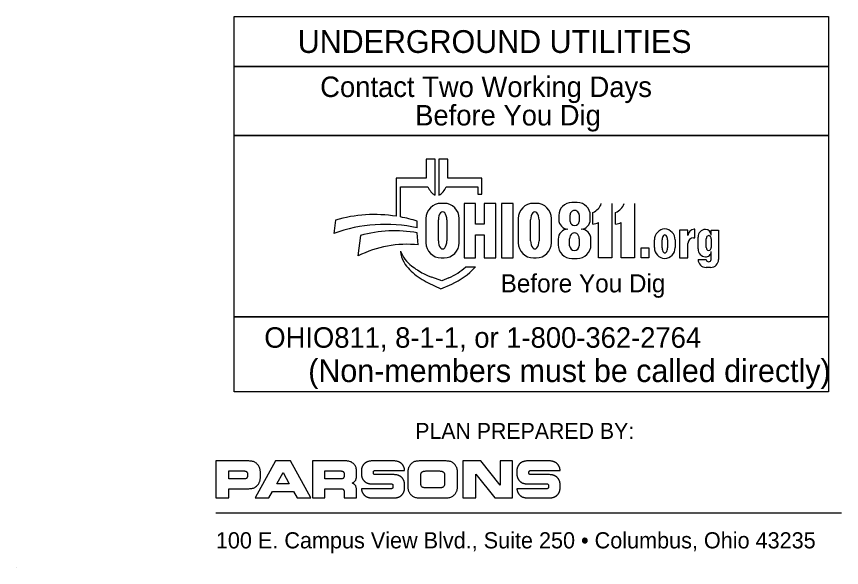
# Model space of a CAD drawing. Extents: x 2080852 to 2433556, y 1080825 to 1306626.
# Drawn here: x 2080852 to 2157439, y 1087161 to 1138301 of the extents above; entities that cross this region are included whole.
import ezdxf

# ---------------------------------------------------------------- set-up
doc = ezdxf.new("R2010")
doc.units = 0
for name, color, linetype in [('PM_P_Chevron_Line', 7, 'Continuous'), ('PM_P_Lane_Line', 7, 'Continuous'), ('SC_Scratch1', 7, 'Continuous')]:
    doc.layers.add(name, color=color, linetype=linetype)

msp = doc.modelspace()

# ---------------------------------------------------------------- linework, layer by layer
at = {"layer": 'PM_P_Chevron_Line'}
for p, q in [((2102311, 1097050), (2099359, 1097050)), ((2104904, 1097050), (2103010, 1093621)), ((2106284, 1097050), (2104904, 1097050)), ((2108178, 1093621), (2106284, 1097050)), ((2111445, 1097050), (2108340, 1097050)), ((2108340, 1097050), (2108340, 1093621)), ((2115910, 1097050), (2113838, 1097050)), ((2120622, 1097050), (2118351, 1097050)), ((2123968, 1097050), (2122290, 1097050)), ((2122290, 1097050), (2122290, 1093621)), ((2125761, 1094812), (2123968, 1097050)), ((2125761, 1097050), (2125761, 1094812)), ((2126893, 1097050), (2125761, 1097050)), ((2126893, 1093621), (2126893, 1097050)), ((2130345, 1097050), (2128273, 1097050)), ((2100576, 1095380), (2100576, 1096117)), ((2100576, 1096117), (2102002, 1096117)), ((2103496, 1095549), (2103496, 1095976)), ((2105012, 1094936), (2105594, 1095990)), ((2105594, 1095990), (2106176, 1094936)), ((2109475, 1095380), (2109475, 1096117)), ((2109475, 1096117), (2110974, 1096117)), ((2112414, 1095633), (2112414, 1096082)), ((2112874, 1096117), (2112874, 1095853)), ((2113987, 1095944), (2113987, 1095994)), ((2114158, 1096159), (2116875, 1096159)), ((2117166, 1095976), (2117166, 1094695)), ((2118857, 1096117), (2120120, 1096117)), ((2121806, 1094695), (2121806, 1095976)), ((2127309, 1096117), (2127309, 1095853)), ((2128422, 1095944), (2128422, 1095994)), ((2128593, 1096159), (2131309, 1096159)), ((2102002, 1095380), (2100576, 1095380)), ((2102287, 1095896), (2102287, 1095602)), ((2110974, 1095380), (2109475, 1095380)), ((2111259, 1095896), (2111259, 1095602)), ((2115910, 1095779), (2114158, 1095779)), ((2118391, 1094928), (2118391, 1095735)), ((2120586, 1095735), (2120586, 1094928)), ((2123484, 1093621), (2123484, 1095817)), ((2123484, 1095817), (2125243, 1093621)), ((2130345, 1095779), (2128593, 1095779)), ((2100576, 1093621), (2100576, 1094475)), ((2100576, 1094475), (2102311, 1094475)), ((2106176, 1094936), (2105012, 1094936)), ((2109475, 1093621), (2109475, 1094475)), ((2109475, 1094475), (2110974, 1094475)), ((2115632, 1094475), (2112874, 1094475)), ((2113838, 1094920), (2115632, 1094920)), ((2115803, 1094755), (2115803, 1094640)), ((2116875, 1094512), (2116875, 1094888)), ((2120120, 1094546), (2118857, 1094546)), ((2130067, 1094475), (2127309, 1094475)), ((2128273, 1094920), (2130067, 1094920)), ((2130238, 1094755), (2130238, 1094640)), ((2131309, 1094512), (2131309, 1094888)), ((2104285, 1093621), (2104606, 1094202)), ((2104606, 1094202), (2106582, 1094202)), ((2106582, 1094202), (2106903, 1093621)), ((2111259, 1094254), (2111259, 1093621)), ((2112414, 1093621), (2112414, 1094361)), ((2103010, 1093621), (2104285, 1093621)), ((2106903, 1093621), (2108178, 1093621)), ((2108340, 1093621), (2109475, 1093621)), ((2111259, 1093621), (2112414, 1093621)), ((2113838, 1093621), (2115910, 1093621)), ((2118351, 1093621), (2120622, 1093621)), ((2122290, 1093621), (2123484, 1093621)), ((2125243, 1093621), (2126893, 1093621)), ((2128273, 1093621), (2130345, 1093621)), ((2099359, 1092220), (2157439, 1092220))]:
    msp.add_line(p, q, dxfattribs=at)
msp.add_lwpolyline([(2099359, 1097050), (2099359, 1093621), (2100576, 1093621)], dxfattribs=at)
for points in [[(2103496, 1095976), (2103492, 1096063), (2103479, 1096175), (2103444, 1096329), (2103408, 1096429), (2103370, 1096510), (2103303, 1096629), (2103226, 1096727), (2103118, 1096829), (2102979, 1096929), (2102853, 1096988), (2102694, 1097023), (2102525, 1097042), (2102311, 1097050)], [(2112414, 1096082), (2112409, 1096239), (2112398, 1096327), (2112370, 1096432), (2112320, 1096560), (2112249, 1096671), (2112165, 1096770), (2112076, 1096852), (2111973, 1096921), (2111845, 1096980), (2111707, 1097019), (2111579, 1097041), (2111445, 1097050)], [(2113145, 1096797), (2113119, 1096770), (2113075, 1096722), (2113035, 1096671), (2113015, 1096644), (2112997, 1096617), (2112980, 1096589), (2112964, 1096560), (2112956, 1096545), (2112949, 1096529), (2112936, 1096497), (2112925, 1096465), (2112914, 1096432), (2112898, 1096380), (2112892, 1096353), (2112886, 1096327), (2112882, 1096305), (2112878, 1096283), (2112875, 1096239), (2112874, 1096117)], [(2113838, 1097050), (2113705, 1097041), (2113641, 1097032), (2113609, 1097026), (2113577, 1097019), (2113507, 1097002), (2113438, 1096980), (2113405, 1096968), (2113373, 1096954), (2113311, 1096921), (2113284, 1096906), (2113258, 1096889), (2113232, 1096871), (2113207, 1096852), (2113184, 1096833), (2113162, 1096813), (2113145, 1096797)], [(2116589, 1096811), (2116587, 1096813), (2116565, 1096833), (2116541, 1096852), (2116517, 1096871), (2116491, 1096889), (2116465, 1096906), (2116438, 1096921), (2116375, 1096954), (2116343, 1096968), (2116310, 1096980), (2116242, 1097002), (2116172, 1097019), (2116140, 1097026), (2116108, 1097032), (2116044, 1097041), (2115910, 1097050)], [(2116875, 1096159), (2116874, 1096239), (2116871, 1096283), (2116867, 1096305), (2116863, 1096327), (2116857, 1096353), (2116850, 1096380), (2116835, 1096432), (2116824, 1096465), (2116812, 1096497), (2116799, 1096529), (2116792, 1096545), (2116785, 1096560), (2116769, 1096589), (2116752, 1096617), (2116733, 1096644), (2116714, 1096671), (2116673, 1096722), (2116630, 1096770), (2116589, 1096811)], [(2118351, 1097050), (2118138, 1097042), (2117968, 1097023), (2117810, 1096988), (2117684, 1096929), (2117545, 1096829), (2117437, 1096727), (2117360, 1096629), (2117293, 1096510), (2117255, 1096429), (2117218, 1096329), (2117183, 1096175), (2117170, 1096063), (2117166, 1095976)], [(2121806, 1095976), (2121803, 1096063), (2121790, 1096175), (2121755, 1096329), (2121718, 1096429), (2121680, 1096510), (2121613, 1096629), (2121536, 1096727), (2121428, 1096829), (2121289, 1096929), (2121163, 1096988), (2121005, 1097023), (2120835, 1097042), (2120622, 1097050)], [(2127580, 1096797), (2127553, 1096770), (2127510, 1096722), (2127470, 1096671), (2127450, 1096644), (2127432, 1096617), (2127415, 1096589), (2127399, 1096560), (2127391, 1096545), (2127384, 1096529), (2127371, 1096497), (2127360, 1096465), (2127349, 1096432), (2127333, 1096380), (2127327, 1096353), (2127321, 1096327), (2127316, 1096305), (2127313, 1096283), (2127310, 1096239), (2127309, 1096117)], [(2128273, 1097050), (2128140, 1097041), (2128076, 1097032), (2128044, 1097026), (2128012, 1097019), (2127942, 1097002), (2127873, 1096980), (2127840, 1096968), (2127808, 1096954), (2127745, 1096921), (2127718, 1096906), (2127692, 1096889), (2127667, 1096871), (2127642, 1096852), (2127619, 1096833), (2127596, 1096813), (2127580, 1096797)], [(2131023, 1096811), (2131022, 1096813), (2131000, 1096833), (2130976, 1096852), (2130951, 1096871), (2130926, 1096889), (2130900, 1096906), (2130873, 1096921), (2130810, 1096954), (2130778, 1096968), (2130745, 1096980), (2130676, 1097002), (2130607, 1097019), (2130575, 1097026), (2130543, 1097032), (2130479, 1097041), (2130345, 1097050)], [(2131309, 1096159), (2131309, 1096239), (2131306, 1096283), (2131302, 1096305), (2131298, 1096327), (2131292, 1096353), (2131285, 1096380), (2131269, 1096432), (2131259, 1096465), (2131247, 1096497), (2131234, 1096529), (2131227, 1096545), (2131220, 1096560), (2131204, 1096589), (2131187, 1096617), (2131168, 1096644), (2131149, 1096671), (2131108, 1096722), (2131065, 1096770), (2131023, 1096811)], [(2102002, 1096117), (2102048, 1096116), (2102159, 1096086), (2102201, 1096061), (2102246, 1096018), (2102280, 1095952), (2102287, 1095913), (2102287, 1095896)], [(2110974, 1096117), (2111020, 1096116), (2111131, 1096086), (2111173, 1096061), (2111218, 1096018), (2111252, 1095952), (2111259, 1095913), (2111259, 1095896)], [(2113987, 1095994), (2113987, 1096027), (2113989, 1096052), (2114005, 1096093), (2114033, 1096127), (2114056, 1096143), (2114105, 1096157), (2114158, 1096159)], [(2118391, 1095735), (2118394, 1095786), (2118400, 1095844), (2118417, 1095901), (2118454, 1095971), (2118515, 1096032), (2118585, 1096070), (2118639, 1096092), (2118730, 1096108), (2118857, 1096117)], [(2120120, 1096117), (2120247, 1096108), (2120339, 1096092), (2120393, 1096070), (2120463, 1096032), (2120524, 1095971), (2120560, 1095901), (2120577, 1095844), (2120584, 1095786), (2120586, 1095735)], [(2128422, 1095994), (2128422, 1096027), (2128424, 1096052), (2128440, 1096093), (2128468, 1096127), (2128491, 1096143), (2128540, 1096157), (2128593, 1096159)], [(2102287, 1095602), (2102287, 1095584), (2102280, 1095545), (2102246, 1095479), (2102201, 1095436), (2102159, 1095411), (2102048, 1095381), (2102002, 1095380)], [(2102311, 1094475), (2102525, 1094482), (2102694, 1094501), (2102853, 1094537), (2102979, 1094596), (2103118, 1094696), (2103226, 1094798), (2103303, 1094896), (2103370, 1095015), (2103408, 1095096), (2103444, 1095195), (2103479, 1095349), (2103492, 1095461), (2103496, 1095549)], [(2111259, 1095602), (2111259, 1095584), (2111252, 1095545), (2111218, 1095479), (2111173, 1095436), (2111131, 1095411), (2111020, 1095381), (2110974, 1095380)], [(2112012, 1094997), (2112107, 1095041), (2112176, 1095082), (2112242, 1095133), (2112304, 1095208), (2112340, 1095267), (2112366, 1095329), (2112398, 1095444), (2112409, 1095552), (2112414, 1095633)], [(2112874, 1095853), (2112875, 1095730), (2112878, 1095687), (2112882, 1095665), (2112886, 1095643), (2112892, 1095616), (2112898, 1095590), (2112914, 1095537), (2112925, 1095505), (2112936, 1095472), (2112949, 1095441), (2112956, 1095425), (2112964, 1095409), (2112980, 1095380), (2112997, 1095353), (2113015, 1095326), (2113035, 1095299), (2113075, 1095248), (2113119, 1095199), (2113145, 1095173)], [(2114158, 1095779), (2114105, 1095781), (2114056, 1095795), (2114033, 1095811), (2114005, 1095845), (2113989, 1095886), (2113987, 1095911), (2113987, 1095944)], [(2116589, 1095541), (2116587, 1095542), (2116565, 1095562), (2116541, 1095581), (2116517, 1095600), (2116491, 1095618), (2116465, 1095635), (2116438, 1095651), (2116375, 1095683), (2116343, 1095697), (2116310, 1095709), (2116242, 1095731), (2116172, 1095748), (2116140, 1095755), (2116108, 1095761), (2116044, 1095770), (2115910, 1095779)], [(2116875, 1094888), (2116874, 1094969), (2116871, 1095012), (2116867, 1095034), (2116863, 1095056), (2116857, 1095082), (2116850, 1095109), (2116835, 1095162), (2116824, 1095194), (2116812, 1095226), (2116799, 1095258), (2116792, 1095274), (2116785, 1095290), (2116769, 1095318), (2116752, 1095346), (2116733, 1095373), (2116714, 1095400), (2116673, 1095451), (2116630, 1095499), (2116589, 1095541)], [(2127309, 1095853), (2127310, 1095730), (2127313, 1095687), (2127316, 1095665), (2127321, 1095643), (2127327, 1095616), (2127333, 1095590), (2127349, 1095537), (2127360, 1095505), (2127371, 1095472), (2127384, 1095441), (2127391, 1095425), (2127399, 1095409), (2127415, 1095380), (2127432, 1095353), (2127450, 1095326), (2127470, 1095299), (2127510, 1095248), (2127553, 1095199), (2127580, 1095173)], [(2128593, 1095779), (2128540, 1095781), (2128491, 1095795), (2128468, 1095811), (2128440, 1095845), (2128424, 1095886), (2128422, 1095911), (2128422, 1095944)], [(2131023, 1095541), (2131022, 1095542), (2131000, 1095562), (2130976, 1095581), (2130951, 1095600), (2130926, 1095618), (2130900, 1095635), (2130873, 1095651), (2130810, 1095683), (2130778, 1095697), (2130745, 1095709), (2130676, 1095731), (2130607, 1095748), (2130575, 1095755), (2130543, 1095761), (2130479, 1095770), (2130345, 1095779)], [(2131309, 1094888), (2131309, 1094969), (2131306, 1095012), (2131302, 1095034), (2131298, 1095056), (2131292, 1095082), (2131285, 1095109), (2131269, 1095162), (2131259, 1095194), (2131247, 1095226), (2131234, 1095258), (2131227, 1095274), (2131220, 1095290), (2131204, 1095318), (2131187, 1095346), (2131168, 1095373), (2131149, 1095400), (2131108, 1095451), (2131065, 1095499), (2131023, 1095541)], [(2110974, 1094475), (2111020, 1094474), (2111131, 1094444), (2111173, 1094419), (2111218, 1094376), (2111252, 1094310), (2111259, 1094271), (2111259, 1094254)], [(2112414, 1094361), (2112409, 1094442), (2112398, 1094550), (2112366, 1094665), (2112340, 1094727), (2112304, 1094786), (2112242, 1094861), (2112176, 1094912), (2112107, 1094953), (2112012, 1094997)], [(2112874, 1094475), (2112875, 1094431), (2112878, 1094388), (2112882, 1094366), (2112886, 1094344), (2112892, 1094318), (2112898, 1094291), (2112914, 1094238), (2112925, 1094206), (2112936, 1094174), (2112949, 1094142), (2112956, 1094126), (2112964, 1094110), (2112980, 1094081), (2112997, 1094054), (2113015, 1094027), (2113035, 1094000), (2113075, 1093949), (2113119, 1093901), (2113162, 1093858), (2113174, 1093847)], [(2113145, 1095173), (2113162, 1095157), (2113184, 1095137), (2113207, 1095118), (2113232, 1095099), (2113258, 1095081), (2113284, 1095064), (2113311, 1095048), (2113373, 1095016), (2113405, 1095002), (2113438, 1094990), (2113507, 1094968), (2113577, 1094951), (2113609, 1094944), (2113641, 1094938), (2113705, 1094929), (2113838, 1094920)], [(2115632, 1094920), (2115685, 1094918), (2115734, 1094904), (2115757, 1094888), (2115785, 1094853), (2115801, 1094813), (2115803, 1094787), (2115803, 1094755)], [(2115803, 1094640), (2115803, 1094607), (2115801, 1094582), (2115785, 1094541), (2115757, 1094507), (2115734, 1094491), (2115685, 1094477), (2115632, 1094475)], [(2116589, 1093859), (2116630, 1093901), (2116673, 1093949), (2116714, 1094000), (2116733, 1094027), (2116752, 1094054), (2116769, 1094081), (2116785, 1094110), (2116792, 1094126), (2116799, 1094142), (2116812, 1094174), (2116824, 1094206), (2116835, 1094238), (2116850, 1094291), (2116857, 1094318), (2116863, 1094344), (2116867, 1094366), (2116871, 1094388), (2116874, 1094431), (2116875, 1094512)], [(2117166, 1094695), (2117170, 1094608), (2117183, 1094496), (2117218, 1094342), (2117255, 1094242), (2117293, 1094161), (2117360, 1094042), (2117437, 1093944), (2117545, 1093842), (2117684, 1093742), (2117810, 1093683), (2117968, 1093648), (2118138, 1093628), (2118351, 1093621)], [(2118857, 1094546), (2118730, 1094555), (2118639, 1094571), (2118585, 1094593), (2118515, 1094631), (2118454, 1094692), (2118417, 1094762), (2118400, 1094819), (2118394, 1094877), (2118391, 1094928)], [(2120586, 1094928), (2120584, 1094877), (2120577, 1094819), (2120560, 1094762), (2120524, 1094692), (2120463, 1094631), (2120393, 1094593), (2120339, 1094571), (2120247, 1094555), (2120120, 1094546)], [(2120622, 1093621), (2120835, 1093628), (2121005, 1093648), (2121163, 1093683), (2121289, 1093742), (2121428, 1093842), (2121536, 1093944), (2121613, 1094042), (2121680, 1094161), (2121718, 1094242), (2121755, 1094342), (2121790, 1094496), (2121803, 1094608), (2121806, 1094695)], [(2127309, 1094475), (2127310, 1094431), (2127313, 1094388), (2127316, 1094366), (2127321, 1094344), (2127327, 1094318), (2127333, 1094291), (2127349, 1094238), (2127360, 1094206), (2127371, 1094174), (2127384, 1094142), (2127391, 1094126), (2127399, 1094110), (2127415, 1094081), (2127432, 1094054), (2127450, 1094027), (2127470, 1094000), (2127510, 1093949), (2127553, 1093901), (2127596, 1093858), (2127609, 1093847)], [(2127580, 1095173), (2127596, 1095157), (2127619, 1095137), (2127642, 1095118), (2127667, 1095099), (2127692, 1095081), (2127718, 1095064), (2127745, 1095048), (2127808, 1095016), (2127840, 1095002), (2127873, 1094990), (2127942, 1094968), (2128012, 1094951), (2128044, 1094944), (2128076, 1094938), (2128140, 1094929), (2128273, 1094920)], [(2130067, 1094920), (2130120, 1094918), (2130169, 1094904), (2130192, 1094888), (2130220, 1094853), (2130236, 1094813), (2130238, 1094787), (2130238, 1094755)], [(2130238, 1094640), (2130238, 1094607), (2130236, 1094582), (2130220, 1094541), (2130192, 1094507), (2130169, 1094491), (2130120, 1094477), (2130067, 1094475)], [(2131023, 1093859), (2131065, 1093901), (2131108, 1093949), (2131149, 1094000), (2131168, 1094027), (2131187, 1094054), (2131204, 1094081), (2131220, 1094110), (2131227, 1094126), (2131234, 1094142), (2131247, 1094174), (2131259, 1094206), (2131269, 1094238), (2131285, 1094291), (2131292, 1094318), (2131298, 1094344), (2131302, 1094366), (2131306, 1094388), (2131309, 1094431), (2131309, 1094512)], [(2113174, 1093847), (2113184, 1093838), (2113207, 1093819), (2113232, 1093800), (2113258, 1093782), (2113284, 1093765), (2113311, 1093749), (2113373, 1093717), (2113405, 1093703), (2113438, 1093691), (2113507, 1093669), (2113577, 1093652), (2113609, 1093645), (2113641, 1093639), (2113705, 1093630), (2113838, 1093621)], [(2115910, 1093621), (2116044, 1093630), (2116108, 1093639), (2116140, 1093645), (2116172, 1093652), (2116242, 1093669), (2116310, 1093691), (2116343, 1093703), (2116375, 1093717), (2116438, 1093749), (2116465, 1093765), (2116491, 1093782), (2116517, 1093800), (2116541, 1093819), (2116565, 1093838), (2116587, 1093858), (2116589, 1093859)], [(2127609, 1093847), (2127619, 1093838), (2127642, 1093819), (2127667, 1093800), (2127692, 1093782), (2127718, 1093765), (2127745, 1093749), (2127808, 1093717), (2127840, 1093703), (2127873, 1093691), (2127942, 1093669), (2128012, 1093652), (2128044, 1093645), (2128076, 1093639), (2128140, 1093630), (2128273, 1093621)], [(2130345, 1093621), (2130479, 1093630), (2130543, 1093639), (2130575, 1093645), (2130607, 1093652), (2130676, 1093669), (2130745, 1093691), (2130778, 1093703), (2130810, 1093717), (2130873, 1093749), (2130900, 1093765), (2130926, 1093782), (2130951, 1093800), (2130976, 1093819), (2131000, 1093838), (2131022, 1093858), (2131023, 1093859)]]:
    msp.add_spline(points, degree=3, dxfattribs=at)
at = {"layer": 'PM_P_Lane_Line'}
for p, q in [((2119728, 1125053), (2118882, 1125053)), ((2118882, 1125053), (2118882, 1123294)), ((2119728, 1121708), (2119728, 1125053)), ((2120903, 1125053), (2120057, 1125053)), ((2120057, 1125053), (2120057, 1121708)), ((2120903, 1123294), (2120903, 1125053)), ((2118882, 1123294), (2116106, 1123294)), ((2116106, 1123294), (2116106, 1119762)), ((2124046, 1123294), (2120903, 1123294)), ((2124046, 1121814), (2124046, 1123294)), ((2116505, 1119693), (2116505, 1122483)), ((2116505, 1122483), (2119046, 1122483)), ((2120738, 1122483), (2123678, 1122483)), ((2123678, 1122483), (2123678, 1121814)), ((2123678, 1121814), (2124046, 1121814)), ((2120538, 1120958), (2120277, 1120958)), ((2123473, 1120943), (2122401, 1120943)), ((2122401, 1120943), (2122401, 1115895)), ((2129100, 1120958), (2128839, 1120958)), ((2132913, 1121027), (2132397, 1121027)), ((2136121, 1120943), (2136121, 1115895)), ((2138234, 1120943), (2138234, 1115895)), ((2131193, 1119823), (2131193, 1119440)), ((2132237, 1119261), (2132237, 1119880)), ((2133091, 1119880), (2133091, 1119261)), ((2134117, 1119440), (2134117, 1119823)), ((2134360, 1119039), (2134360, 1120114)), ((2136473, 1119039), (2136473, 1120114)), ((2110456, 1119401), (2110308, 1118169)), ((2118048, 1118686), (2118048, 1119299)), ((2118866, 1119547), (2118866, 1117306)), ((2120016, 1117486), (2120016, 1119416)), ((2120802, 1119416), (2120802, 1117486)), ((2121950, 1117306), (2121950, 1119547)), ((2127428, 1119547), (2127428, 1117306)), ((2128578, 1117486), (2128578, 1119416)), ((2129363, 1119416), (2129363, 1117486)), ((2130511, 1117306), (2130511, 1119547)), ((2134870, 1115895), (2134870, 1119186)), ((2136983, 1115895), (2136983, 1119186)), ((2118155, 1117097), (2118056, 1118216)), ((2143184, 1118466), (2142413, 1118466)), ((2142413, 1118466), (2142413, 1115895)), ((2143184, 1117968), (2143184, 1118466)), ((2143825, 1118547), (2143763, 1118547)), ((2143825, 1117761), (2143825, 1118547)), ((2145337, 1117991), (2145337, 1118480)), ((2145337, 1118480), (2146024, 1118480)), ((2146024, 1118480), (2146024, 1115753)), ((2112786, 1117973), (2112554, 1116078)), ((2123473, 1115895), (2123473, 1118029)), ((2131135, 1117644), (2131135, 1117107)), ((2132199, 1117013), (2132199, 1117658)), ((2133096, 1117658), (2133096, 1117013)), ((2134181, 1117107), (2134181, 1117644)), ((2140069, 1116855), (2140069, 1117570)), ((2140779, 1116842), (2140779, 1117570)), ((2141286, 1117570), (2141286, 1116842)), ((2141996, 1117570), (2141996, 1116855)), ((2143704, 1117761), (2143825, 1117761)), ((2144123, 1116722), (2144123, 1117820)), ((2144886, 1116869), (2144886, 1117674)), ((2145337, 1117674), (2145337, 1116869)), ((2143184, 1115895), (2143184, 1117240)), ((2116494, 1116530), (2116543, 1116247)), ((2120277, 1115895), (2120538, 1115895)), ((2122401, 1115895), (2123473, 1115895)), ((2128839, 1115895), (2129100, 1115895)), ((2136121, 1115895), (2134870, 1115895)), ((2138234, 1115895), (2136983, 1115895)), ((2142413, 1115895), (2143184, 1115895)), ((2145337, 1115753), (2145337, 1116485)), ((2132412, 1115830), (2132904, 1115830)), ((2144123, 1115753), (2144886, 1115753)), ((2123447, 1115050), (2122542, 1115050)), ((2123422, 1115022), (2123447, 1115050)), ((2145286, 1115015), (2144861, 1115015)), ((2120349, 1113775), (2119411, 1114098)), ((2120996, 1114056), (2120349, 1113775)), ((2119665, 1113293), (2120254, 1113033)), ((2120254, 1113033), (2121252, 1113466)), ((2156224, 1103453), (2101048, 1103453))]:
    msp.add_line(p, q, dxfattribs=at)
for points in [[(2101048, 1138301), (2156224, 1138301), (2156224, 1133654), (2101048, 1133654)], [(2101048, 1133654), (2156224, 1133654), (2156224, 1127265), (2101048, 1127265)], [(2101048, 1127265), (2156224, 1127265), (2156224, 1110422), (2101048, 1110422)], [(2138847, 1116842), (2139542, 1116842), (2139542, 1115895), (2138847, 1115895)], [(2101048, 1110422), (2156224, 1110422), (2156224, 1103453), (2101048, 1103453)]]:
    msp.add_lwpolyline(points, close=True, dxfattribs=at)
for points in [[(2123473, 1118029), (2124277, 1118029), (2124277, 1115895), (2125349, 1115895), (2125349, 1120943), (2124277, 1120943), (2124277, 1119039), (2123473, 1119039), (2123473, 1120943)], [(2125885, 1115895), (2126970, 1115895), (2126970, 1120943), (2125885, 1120943), (2125885, 1115895)], [(2132048, 1118557), (2132048, 1118557)], [(2133268, 1118557), (2133268, 1118557)]]:
    msp.add_lwpolyline(points, dxfattribs=at)
for centre, radius, start, end in [((2120487, 1123063), 1553, 201.92963, 240.74693), ((2119297, 1123063), 1553, 299.25307, 338.07037), ((2120277, 1119547), 1411, 90, 180), ((2120538, 1119547), 1411, 0, 90), ((2128839, 1119547), 1411, 90, 180), ((2129100, 1119547), 1411, 0, 90), ((2132397, 1119823), 1204, 90, 180), ((2132913, 1119823), 1204, 0, 90), ((2133825, 1121403), 1396, 292.55722, 340.73552), ((2135938, 1121403), 1396, 292.55722, 340.73552), ((2114085, 1107001), 12921, 81.00071, 106.31438), ((2115080, 1104933), 14070, 77.82382, 109.82736), ((2114085, 1107001), 12921, 72.14025, 79.20744), ((2132076, 1119440), 883, 180, 268.14422), ((2133234, 1119440), 883, 272.20579, 0), ((2134234, 1120429), 1396, 275.17327, 297.09312), ((2136347, 1120429), 1396, 275.17327, 297.09312), ((2115940, 1106862), 11550, 79.44002, 105.84672), ((2132048, 1117644), 913, 90, 180), ((2133268, 1117644), 913, 0, 90), ((2141078, 1117570), 1009, 92.58863, 180), ((2140987, 1117570), 1009, 0, 87.41137), ((2143763, 1117968), 579, 90, 180), ((2144847, 1117820), 724, 92.68649, 180), ((2144784, 1117991), 553, 0, 86.92624), ((2143704, 1117240), 520, 90, 180), ((2117076, 1107127), 10028, 83.82483, 116.80206), ((2120277, 1117306), 1411, 180, 270), ((2120538, 1117306), 1411, 270, 0), ((2128839, 1117306), 1411, 180, 270), ((2129100, 1117306), 1411, 270, 0), ((2132412, 1117107), 1277, 180, 270), ((2132904, 1117107), 1277, 270, 0), ((2141078, 1116855), 1009, 180, 267.41137), ((2140987, 1116855), 1009, 272.58863, 0), ((2144854, 1116722), 730, 180, 265.71324), ((2119450, 1117668), 3167, 201.04565, 232.53137), ((2118772, 1116628), 2261, 189.68174, 216.08842), ((2144844, 1116485), 493, 264.78254, 0), ((2120880, 1118165), 4871, 216.08842, 235.7167), ((2122488, 1121630), 8160, 232.53137, 241.79401), ((2144861, 1115753), 738, 180, 270), ((2145286, 1115753), 738, 270, 0), ((2121144, 1119125), 5317, 241.79401, 250.98207), ((2118734, 1119269), 5683, 293.45821, 312.07118), ((2118734, 1119269), 6325, 293.45821, 317.82862), ((2123507, 1122018), 9534, 235.7167, 246.23245)]:
    msp.add_arc(centre, radius, start, end, dxfattribs=at)
for centre, major_axis, ratio, start_param, end_param in [((2120409, 1119416), (0, 764), 0.514403, 4.712389, 7.853982), ((2128970, 1119416), (0, 764), 0.514403, 4.712389, 7.853982), ((2132664, 1119880), (427, 0), 0.969373, 0, 3.141593), ((2132664, 1119261), (427, 0), 0.818453, 3.141593, 6.283185), ((2132648, 1117658), (0, 564), 0.794529, 4.712389, 7.853982), ((2120409, 1117486), (0, 764), 0.514403, 1.570796, 4.712389), ((2128970, 1117486), (0, 764), 0.514403, 1.570796, 4.712389), ((2141033, 1117570), (0, 459), 0.553236, 4.712389, 7.853982), ((2145111, 1117674), (0, 290), 0.777179, 4.712389, 7.853982), ((2132648, 1117013), (448, 0), 0.959837, 3.141593, 6.283185), ((2141033, 1116842), (0, 486), 0.522014, 1.570796, 4.712389), ((2145111, 1116869), (0, 290), 0.777179, 1.570796, 4.712389), ((2145111, 1115753), (226, 0), 0.959012, 3.141593, 6.283185)]:
    msp.add_ellipse(centre, major_axis=major_axis, ratio=ratio, start_param=start_param, end_param=end_param, dxfattribs=at)
at = {"layer": 'SC_Scratch1'}
msp.add_line((2080852, 1087161), (2080852, 1087161), dxfattribs=at)

# ---------------------------------------------------------------- texts
at = {"layer": 'PM_P_Chevron_Line'}
msp.add_text('100 E. Campus View Blvd., Suite 250 • Columbus, Ohio 43235', height=1500.31, dxfattribs=at).set_placement((2099359, 1088933))
at = {"layer": 'PM_P_Lane_Line'}
for s, height, p in [('UNDERGROUND UTILITIES', 2112, (2106959, 1134921)), ('Contact Two Working Days', 1900.8, (2109045, 1130829)), ('Before You Dig', 1900.8, (2117862, 1128189)), ('Before You Dig', 1686.64, (2125795, 1112696)), ('OHIO811, 8-1-1, or 1-800-362-2764', 1900.8, (2103855, 1107557)), ('(Non-members must be called directly)', 2112, (2107934, 1104372)), ('PLAN PREPARED BY:', 1478.4, (2117868, 1099097))]:
    msp.add_text(s, height=height, dxfattribs=at).set_placement(p)

doc.saveas('drawing.dxf')
